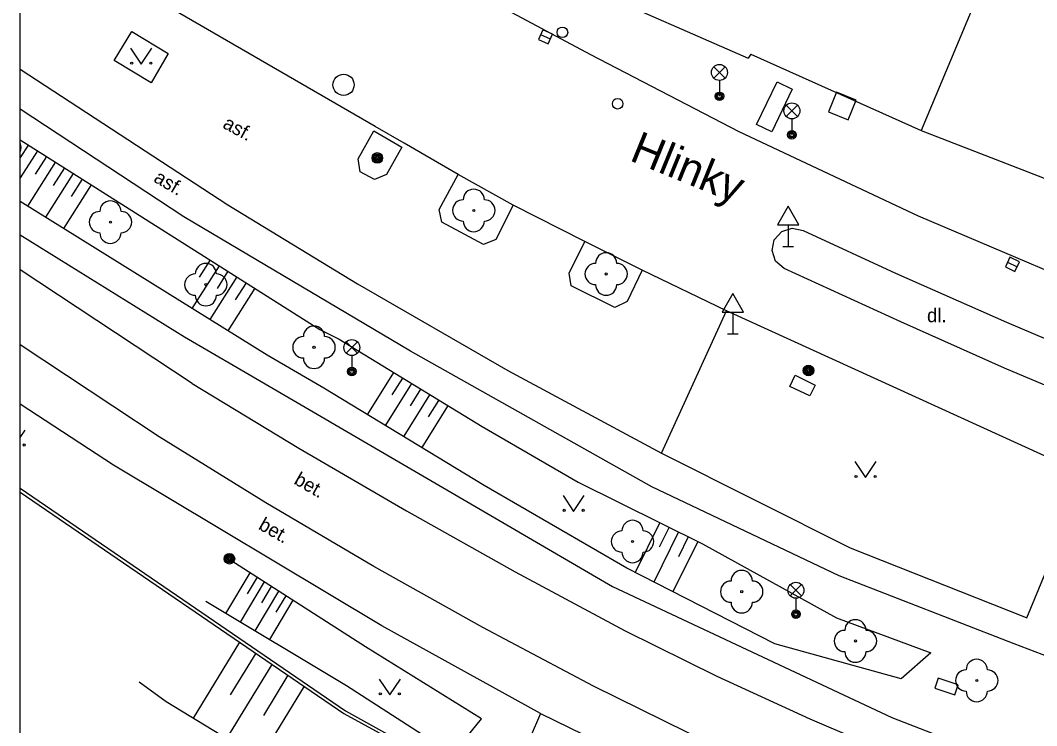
# Model space of a CAD drawing. Extents: x -600309 to -598967, y -1161267 to -1160292.
# Drawn here: x -600308.54 to -600260.71, y -1161054.96 to -1161021.76 of the extents above; entities that cross this region are included whole.
import ezdxf

# ---------------------------------------------------------------- set-up
doc = ezdxf.new("R2010")
doc.units = 0
for name, color, linetype in [('Level 10', 7, 'Continuous'), ('Level 11', 7, 'Continuous'), ('Level 13', 7, 'Continuous'), ('Level 14', 7, 'Continuous'), ('Level 15', 7, 'Continuous'), ('Level 22', 7, 'Continuous'), ('Level 24', 7, 'Continuous'), ('Level 25', 7, 'Continuous'), ('Level 26', 7, 'Continuous'), ('Level 27', 7, 'Continuous'), ('Level 28', 7, 'Continuous'), ('Level 33', 7, 'Continuous'), ('Level 34', 7, 'Continuous'), ('Level 36', 7, 'Continuous'), ('Level 40', 7, 'Continuous'), ('Level 49', 7, 'Continuous'), ('Level 5', 7, 'Continuous'), ('Level 7', 7, 'Continuous'), ('Vrstva 63', 7, 'Continuous')]:
    doc.layers.add(name, color=color, linetype=linetype)

msp = doc.modelspace()

# ---------------------------------------------------------------- linework, layer by layer
at = {"layer": 'Level 10'}
for points in [[(-600287.94, -1161029.02), (-600290.4833, -1161027.5503), (-600291.8481, -1161026.7616), (-600301.04, -1161021.45), (-600308.541, -1161016.7741)], [(-600290.05, -1161018.9099), (-600281.71, -1161023.37)], [(-600281.71, -1161023.37), (-600274.7199, -1161027)], [(-600274.7199, -1161027), (-600266.28, -1161030.9699), (-600255.36, -1161035.6)], [(-600285.35, -1161030.46), (-600287.94, -1161029.02)], [(-600281.9699, -1161032.17), (-600285.35, -1161030.46)], [(-600257.23, -1161040.24), (-600262.23, -1161038.14), (-600267.1, -1161035.96), (-600272.6, -1161033.44), (-600273, -1161033.1), (-600273.1599, -1161032.6), (-600273.06, -1161032.09), (-600272.71, -1161031.7), (-600272.21, -1161031.54), (-600271.7, -1161031.65)], [(-600271.7, -1161031.65), (-600267.35, -1161033.6599), (-600262.13, -1161035.9699), (-600256.48, -1161038.37)], [(-600279.28, -1161033.52), (-600281.9699, -1161032.17)], [(-600275.3, -1161035.43), (-600279.28, -1161033.52)], [(-600258.38, -1161043.15), (-600275.3, -1161035.43)]]:
    msp.add_lwpolyline(points, dxfattribs=at)
at = {"layer": 'Level 11'}
for points in [[(-600304.13, -1161023.6599), (-600303.29, -1161022.29), (-600301.59, -1161023.33), (-600302.39, -1161024.71), (-600304.13, -1161023.6599)], [(-600308.541, -1161024.0646), (-600298.77, -1161030.45), (-600292.68, -1161034.1599), (-600285.6, -1161038.24), (-600278.36, -1161042.14)], [(-600273.89, -1161026.6599), (-600272.93, -1161024.6599), (-600272.21, -1161025.01), (-600273.18, -1161027.01), (-600273.89, -1161026.6599)], [(-600259.4699, -1161051.99), (-600261.7686, -1161051.1002), (-600270.01, -1161047.9099), (-600278.82, -1161043.71), (-600290.18, -1161037.34), (-600300.84, -1161031.01), (-600308.541, -1161025.9449)], [(-600292.64, -1161028.29), (-600291.9099, -1161026.96), (-600290.58, -1161027.73), (-600291.31, -1161029.02), (-600291.88, -1161029.26), (-600292.55, -1161028.89), (-600292.64, -1161028.29)], [(-600285.35, -1161030.46), (-600286.17, -1161032.08), (-600286.74, -1161032.32), (-600288.7, -1161031.26), (-600288.83, -1161030.6599), (-600287.94, -1161029.02)], [(-600308.541, -1161031.8538), (-600300.81, -1161036.6599), (-600298.3408, -1161038.1005), (-600280.67, -1161048.4099), (-600267.52, -1161054.57), (-600256.42, -1161058.89)], [(-600279.28, -1161033.52), (-600279.98, -1161034.99), (-600280.56, -1161035.28), (-600282.62, -1161034.26), (-600282.71, -1161033.67), (-600281.9699, -1161032.17)], [(-600278.36, -1161042.14), (-600275.3, -1161035.43)], [(-600284.06, -1161054.38), (-600291.53, -1161050.26), (-600304.15, -1161042.69), (-600308.541, -1161039.8253)], [(-600278.36, -1161042.14), (-600269.48, -1161046.58), (-600261.2896, -1161049.8377), (-600261.18, -1161049.88), (-600258.61, -1161043.7)], [(-600284.06, -1161054.38), (-600285.04, -1161056.64)], [(-600284.06, -1161054.38), (-600276.71, -1161057.9699), (-600268.4699, -1161061.55), (-600258.71, -1161065.46), (-600258.38, -1161064.83)]]:
    msp.add_lwpolyline(points, dxfattribs=at)
at = {"layer": 'Level 13'}
for p, q in [((-600300.46, -1161038.85), (-600308.541, -1161033.5126)), ((-600302, -1161041.36), (-600308.541, -1161037.0397))]:
    msp.add_line(p, q, dxfattribs=at)
for points in [[(-600300.46, -1161038.85), (-600295.44, -1161041.89), (-600290.37, -1161044.85), (-600285.25, -1161047.71), (-600280.08, -1161050.49), (-600275.76, -1161052.63), (-600271.38, -1161054.64), (-600266.94, -1161056.53), (-600262.45, -1161058.28)], [(-600263.57, -1161061.2), (-600268.14, -1161059.34), (-600272.6599, -1161057.36), (-600277.14, -1161055.28), (-600281.56, -1161053.09), (-600286.77, -1161050.33), (-600291.9099, -1161047.46), (-600296.99, -1161044.4699), (-600302, -1161041.36)]]:
    msp.add_lwpolyline(points, dxfattribs=at)
at = {"layer": 'Level 14'}
for points in [[(-600308.541, -1161027.3869), (-600294.44, -1161036.31), (-600293.53, -1161036.77), (-600286.81, -1161040.87), (-600282.29, -1161043.5), (-600276.43, -1161046.4), (-600270.13, -1161049.88), (-600265.69, -1161051.53)], [(-600265.69, -1161051.53), (-600267.09, -1161052.75), (-600273.04, -1161051.11), (-600279.99, -1161047.55), (-600286.71, -1161043.65), (-600294.25, -1161039.07), (-600296.93, -1161037.52), (-600308.541, -1161030.296)], [(-600289.19, -1161057.54), (-600286.84, -1161054.64), (-600292.3, -1161051.24), (-600298.64, -1161047.18)], [(-600289.11, -1161056.54), (-600289.61, -1161055.39), (-600293.19, -1161053.08), (-600299.81, -1161049.11)], [(-600286.59, -1161061.69), (-600287.59, -1161061.27), (-600295.83, -1161057.4), (-600301.68, -1161053.83), (-600302.95, -1161052.9099)]]:
    msp.add_lwpolyline(points, dxfattribs=at)
at = {"layer": 'Level 15'}
for p, q in [((-600308.1599, -1161027.63), (-600308.541, -1161028.2266)), ((-600307.74, -1161027.9), (-600308.541, -1161029.1717))]:
    msp.add_line(p, q, dxfattribs=at)
for points in [[(-600306.89, -1161028.43), (-600308.2, -1161030.51)], [(-600307.31, -1161028.17), (-600307.84, -1161029)], [(-600306.05, -1161028.9699), (-600307.35, -1161031.03)], [(-600306.4699, -1161028.7), (-600306.99, -1161029.53)], [(-600305.63, -1161029.24), (-600306.15, -1161030.06)], [(-600305.2, -1161029.5), (-600306.51, -1161031.56)], [(-600299.61, -1161033.04), (-600300.12, -1161033.85)], [(-600299.19, -1161033.31), (-600300.4699, -1161035.32)], [(-600298.77, -1161033.57), (-600299.28, -1161034.38)], [(-600298.35, -1161033.84), (-600299.62, -1161035.85)], [(-600297.92, -1161034.11), (-600298.43, -1161034.9099)], [(-600297.5, -1161034.37), (-600298.77, -1161036.38)], [(-600290.98, -1161038.33), (-600292.2, -1161040.29)], [(-600290.13, -1161038.86), (-600291.35, -1161040.81)], [(-600290.56, -1161038.6), (-600291.05, -1161039.38)], [(-600289.29, -1161039.39), (-600290.5, -1161041.33)], [(-600289.71, -1161039.12), (-600290.19, -1161039.9)], [(-600288.44, -1161039.92), (-600289.64, -1161041.86)], [(-600288.86, -1161039.65), (-600289.35, -1161040.43)], [(-600278.45, -1161045.4), (-600279.61, -1161047.74)], [(-600278, -1161045.62), (-600278.4699, -1161046.56)], [(-600277.56, -1161045.84), (-600278.7199, -1161048.2)], [(-600277.11, -1161046.07), (-600277.57, -1161047.01)], [(-600276.6599, -1161046.29), (-600277.83, -1161048.6599)], [(-600297.74, -1161047.76), (-600298.88, -1161049.67)], [(-600297.4, -1161047.9699), (-600297.87, -1161048.75)], [(-600297.06, -1161048.19), (-600298.2, -1161050.08)], [(-600296.73, -1161048.4099), (-600297.19, -1161049.18)], [(-600296.39, -1161048.62), (-600297.51, -1161050.49)], [(-600295.7199, -1161049.05), (-600296.82, -1161050.9)], [(-600296.05, -1161048.84), (-600296.51, -1161049.61)], [(-600298.2199, -1161051.03), (-600300.4099, -1161054.6)], [(-600297.46, -1161051.55), (-600298.6599, -1161053.51)], [(-600296.7, -1161052.07), (-600298.84, -1161055.56)], [(-600295.95, -1161052.58), (-600297.1, -1161054.48)], [(-600295.19, -1161053.1), (-600297.27, -1161056.52)]]:
    msp.add_lwpolyline(points, dxfattribs=at)
at = {"layer": 'Level 22'}
for centre in [(-600287.2, -1161030.71), (-600304.3, -1161031.26), (-600280.9699, -1161033.7), (-600299.81, -1161034.2), (-600294.7199, -1161037.15), (-600279.73, -1161046.29), (-600274.59, -1161048.65), (-600269.24, -1161050.9699), (-600263.53, -1161052.83)]:
    msp.add_circle(centre, 0.05, dxfattribs=at)
for centre, start, end in [((-600309, -1161027.75), 336.64829, 23.35171), ((-600287.2, -1161030.21), 0, 180), ((-600304.3, -1161030.76), 0, 180), ((-600287.7, -1161030.71), 90, 270), ((-600286.7, -1161030.71), 270, 90), ((-600304.8, -1161031.26), 90, 270), ((-600303.8, -1161031.26), 270, 90), ((-600287.2, -1161031.21), 180, 0), ((-600304.3, -1161031.76), 180, 0), ((-600280.9699, -1161033.2), 0, 180), ((-600299.81, -1161033.7), 0, 180), ((-600281.4699, -1161033.7), 90, 270), ((-600280.4699, -1161033.7), 270, 90), ((-600300.31, -1161034.2), 90, 270), ((-600299.31, -1161034.2), 270, 90), ((-600280.9699, -1161034.2), 180, 0), ((-600299.81, -1161034.7), 180, 0), ((-600294.7199, -1161036.65), 0, 180), ((-600295.2199, -1161037.15), 90, 270), ((-600294.2199, -1161037.15), 270, 90), ((-600294.7199, -1161037.65), 180, 0), ((-600279.73, -1161045.79), 0, 180), ((-600280.23, -1161046.29), 90, 270), ((-600279.23, -1161046.29), 270, 90), ((-600279.73, -1161046.79), 180, 0), ((-600274.59, -1161048.15), 0, 180), ((-600275.09, -1161048.65), 90, 270), ((-600274.09, -1161048.65), 270, 90), ((-600274.59, -1161049.15), 180, 0), ((-600269.24, -1161050.4699), 0, 180), ((-600269.74, -1161050.9699), 90, 270), ((-600268.74, -1161050.9699), 270, 90), ((-600269.24, -1161051.4699), 180, 0), ((-600263.53, -1161052.33), 0, 180), ((-600264.03, -1161052.83), 90, 270), ((-600263.03, -1161052.83), 270, 90), ((-600263.53, -1161053.33), 180, 0)]:
    msp.add_arc(centre, 0.5, start, end, dxfattribs=at)
at = {"layer": 'Level 24'}
msp.add_lwpolyline([(-600272.08, -1161038.46), (-600271.13, -1161038.93), (-600271.38, -1161039.44), (-600272.33, -1161039), (-600272.08, -1161038.46)], dxfattribs=at)
msp.add_lwpolyline([(-600265.5032, -1161053.1902), (-600264.5539, -1161053.5045), (-600264.3968, -1161053.0298), (-600265.3461, -1161052.7155)], close=True, dxfattribs=at)
at = {"layer": 'Level 25'}
for centre, radius in [((-600291.74, -1161028.24), 0.25), ((-600291.74, -1161028.24), 0.2), ((-600291.74, -1161028.24), 0.15), ((-600291.74, -1161028.24), 0.1), ((-600291.74, -1161028.24), 0.05), ((-600271.45, -1161038.24), 0.25), ((-600271.45, -1161038.24), 0.2), ((-600271.45, -1161038.24), 0.15), ((-600271.45, -1161038.24), 0.1), ((-600271.45, -1161038.24), 0.05), ((-600298.7, -1161047.1), 0.25), ((-600298.7, -1161047.1), 0.2), ((-600298.7, -1161047.1), 0.15), ((-600298.7, -1161047.1), 0.1), ((-600298.7, -1161047.1), 0.05)]:
    msp.add_circle(centre, radius, dxfattribs=at)
at = {"layer": 'Level 26'}
msp.add_lwpolyline([(-600270.5131, -1161026.0709), (-600269.5891, -1161026.4531), (-600269.2069, -1161025.5291), (-600270.1309, -1161025.1469)], close=True, dxfattribs=at)
at = {"layer": 'Level 27'}
for p, q in [((-600284.0582, -1161022.438), (-600283.6018, -1161022.642)), ((-600262.0756, -1161033.1424), (-600261.6244, -1161033.3576))]:
    msp.add_line(p, q, dxfattribs=at)
for points in [[(-600284.1602, -1161022.6662), (-600283.7038, -1161022.8702), (-600283.4998, -1161022.4138), (-600283.9562, -1161022.2098)], [(-600262.1833, -1161033.368), (-600261.732, -1161033.5833), (-600261.5167, -1161033.132), (-600261.968, -1161032.9167)]]:
    msp.add_lwpolyline(points, close=True, dxfattribs=at)
msp.add_circle((-600293.33, -1161024.8), 0.5, dxfattribs=at)
at = {"layer": 'Level 28'}
for centre in [(-600283.03, -1161022.33), (-600280.43, -1161025.69)]:
    msp.add_circle(centre, 0.25, dxfattribs=at)
at = {"layer": 'Level 33'}
for p, q in [((-600275.905, -1161024.48), (-600275.375, -1161023.95)), ((-600275.905, -1161023.95), (-600275.375, -1161024.48)), ((-600275.64, -1161024.59), (-600275.64, -1161025.34)), ((-600272.495, -1161026.29), (-600271.965, -1161025.76)), ((-600272.495, -1161025.76), (-600271.965, -1161026.29)), ((-600272.23, -1161026.4), (-600272.23, -1161027.15)), ((-600293.205, -1161037.43), (-600292.675, -1161036.9)), ((-600293.205, -1161036.9), (-600292.675, -1161037.43)), ((-600292.94, -1161037.54), (-600292.94, -1161038.29)), ((-600272.305, -1161048.85), (-600271.775, -1161048.32)), ((-600272.305, -1161048.32), (-600271.775, -1161048.85)), ((-600272.04, -1161048.96), (-600272.04, -1161049.71))]:
    msp.add_line(p, q, dxfattribs=at)
for centre, radius in [((-600275.64, -1161024.215), 0.375), ((-600275.64, -1161025.34), 0.2), ((-600275.64, -1161025.34), 0.1445), ((-600275.64, -1161025.34), 0.0876), ((-600272.23, -1161026.025), 0.375), ((-600272.23, -1161027.15), 0.2), ((-600272.23, -1161027.15), 0.1445), ((-600272.23, -1161027.15), 0.0876), ((-600292.94, -1161037.165), 0.375), ((-600292.94, -1161038.29), 0.2), ((-600292.94, -1161038.29), 0.1445), ((-600292.94, -1161038.29), 0.0876), ((-600272.04, -1161048.585), 0.375), ((-600272.04, -1161049.71), 0.2), ((-600272.04, -1161049.71), 0.1445), ((-600272.04, -1161049.71), 0.0876)]:
    msp.add_circle(centre, radius, dxfattribs=at)
at = {"layer": 'Level 34'}
for p, q in [((-600272.4099, -1161031.382), (-600272.4099, -1161032.4)), ((-600272.6599, -1161032.4), (-600272.1599, -1161032.4)), ((-600275.01, -1161035.492), (-600275.01, -1161036.51)), ((-600275.26, -1161036.51), (-600274.76, -1161036.51))]:
    msp.add_line(p, q, dxfattribs=at)
for points in [[(-600272.9099, -1161031.382), (-600271.9099, -1161031.382), (-600272.4099, -1161030.516)], [(-600275.51, -1161035.492), (-600274.51, -1161035.492), (-600275.01, -1161034.626)]]:
    msp.add_lwpolyline(points, close=True, dxfattribs=at)
at = {"layer": 'Level 36'}
msp.add_line((-600308.541, -1161041.3964), (-600308.31, -1161041.05), dxfattribs=at)
for points in [[(-600303.35, -1161023.08), (-600302.85, -1161023.83), (-600302.35, -1161023.08)], [(-600269.26, -1161042.53), (-600268.76, -1161043.28), (-600268.26, -1161042.53)], [(-600283, -1161044.12), (-600282.5, -1161044.87), (-600282, -1161044.12)], [(-600291.65, -1161052.76), (-600291.15, -1161053.51), (-600290.65, -1161052.76)]]:
    msp.add_lwpolyline(points, dxfattribs=at)
for centre in [(-600303.3002, -1161023.7798), (-600302.4008, -1161023.7798), (-600308.3608, -1161041.7498), (-600269.2102, -1161043.2298), (-600268.3108, -1161043.2298), (-600282.9502, -1161044.8198), (-600282.0508, -1161044.8198), (-600291.6002, -1161053.4598), (-600290.7008, -1161053.4598)]:
    msp.add_circle(centre, 0.05, dxfattribs=at)
at = {"layer": 'Level 5'}
for points in [[(-600260.96, -1161014.55), (-600266.14, -1161026.95)], [(-600281.9, -1161020.2), (-600274.28, -1161023.54)], [(-600274.1599, -1161023.35), (-600274.28, -1161023.54)], [(-600274.1599, -1161023.35), (-600266.14, -1161026.95)], [(-600266.14, -1161026.95), (-600251.86, -1161032.49)]]:
    msp.add_lwpolyline(points, dxfattribs=at)
at = {"layer": 'Level 7'}
for p, q in [((-600308.541, -1161043.785), (-600293.23, -1161054.26)), ((-600308.541, -1161043.9697), (-600293.31, -1161054.39))]:
    msp.add_line(p, q, dxfattribs=at)
for points in [[(-600293.23, -1161054.26), (-600289.11, -1161056.54)], [(-600293.31, -1161054.39), (-600289.1599, -1161056.6599)]]:
    msp.add_lwpolyline(points, dxfattribs=at)
at = {"layer": 'Vrstva 63'}
msp.add_lwpolyline([(-600308.541, -1160292.3474), (-598967.1085, -1160292.3474), (-598967.1085, -1161267.0314), (-600308.541, -1161267.0314)], close=True, dxfattribs=at)

# ---------------------------------------------------------------- texts
at = {"layer": 'Level 40'}
for s, rotation, p in [('asf.', 331.34, (-600299.06, -1161026.8)), ('asf.', 329.4, (-600302.31, -1161029.33)), ('bet.', 330.18, (-600295.71, -1161043.55)), ('bet.', 330.18, (-600297.38, -1161045.68))]:
    msp.add_text(s, height=0.65, rotation=rotation, dxfattribs=at).set_placement(p)
msp.add_text('dl.', height=0.65, dxfattribs=at).set_placement((-600265.87, -1161035.9699))
at = {"layer": 'Level 49'}
msp.add_text('Hlinky', height=1.5, rotation=337.83, dxfattribs=at).set_placement((-600279.92, -1161028.34))

doc.saveas('drawing.dxf')
